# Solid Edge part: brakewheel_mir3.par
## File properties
Author: KULL
Template: Iso Metric Part.par
Last saved by: KULL
Revision: 2
Application: Solid Edge
Accuracy: 0,990
Username: KULL
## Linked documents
brakewheel.par
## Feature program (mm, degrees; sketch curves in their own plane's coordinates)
part copy "CopiedPart_1"
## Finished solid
Body 1: solid body, 544 faces, 1066 edges, 432 vertices.
  Faces by surface: torus 226, cylinder 204, blend 72, plane 42
  Edges by curve: circle 742, intersection 216, line 108
Bounding box of the edges (mm; curved faces can reach further): 52.000 x 5.000 x 52.000, from (-26, -123, -3) to (26, -118, 49).
Cylindrical faces by radius (mm): R0.2 x36, R0.7 x36, R0.8 x36, R0.9 x36, R4 x1, R10 x2, R14.7173 x18, R15 x2, R17 x18, R26 x1, R28.4 x18
Toroidal faces (ring radius, tube radius in mm): R0.8 r0.1 x36, R0.9 r0.1 x36, R1 r0.1 x36, R9.8 r0.2 x2, R10.2 r0.2 x2, R14.8 r0.2 x2, R15.1173 r0.4 x36, R15.2 r0.2 x2, R25.8 r0.2 x38, R28 r0.4 x36
Planar faces by outward normal: +y 21, -y 21
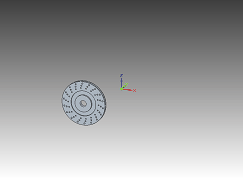
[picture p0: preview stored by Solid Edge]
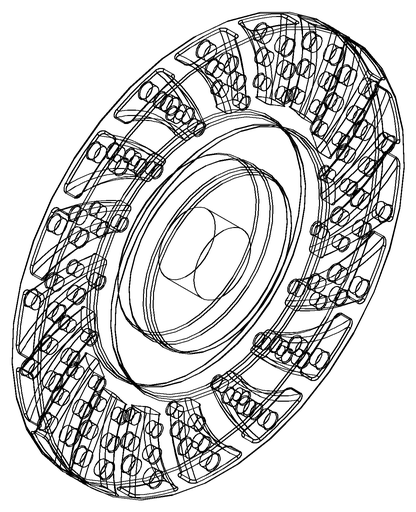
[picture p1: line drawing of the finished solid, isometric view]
